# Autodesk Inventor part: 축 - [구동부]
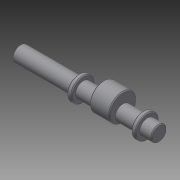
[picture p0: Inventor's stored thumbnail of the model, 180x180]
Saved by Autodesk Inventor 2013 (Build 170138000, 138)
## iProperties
Company: 한국ATC센터
Created: 2014-08
Part Number: 축 - [구동부]
Document SubType Name: Modeling
Designer: KYOUNG IL JANG
Density: 1 g/cm^3
Material: 일반
Author: KYOUNG IL JANG
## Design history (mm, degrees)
sketch "스케치1"
  geometry: L1 (-76.5, 0)-(76.5, 0); L2 (-76.5, 0)-(-76.5, 8.5); L3 (-76.5, 8.5)-(-12.5, 8.5); L4 (-12.5, 8.5)-(-12.5, 13); L5 (-12.5, 13)-(-7.5, 13); L6 (-7.5, 13)-(-7.5, 8.5); L7 (-7.5, 8.5)-(58.5, 8.5); L8 (58.5, 8.5)-(58.5, 13); L9 (58.5, 13)-(63.5, 13); L10 (63.5, 13)-(63.5, 8.5); L11 (63.5, 8.5)-(76.5, 8.5); L12 (76.5, 8.5)-(76.5, 0); 2 further points
  constraints: 24 end point, 5 parallel, 1 coincident, 1 horizontal, 1 midpoint, 1 perpendicular
  dimensions: "d0" = 153 distance of L1.start L1.end (derived); "d2" = 17 diameter of L3 L1; "d3" = 26 diameter of L5 L1; "d4" = 17 diameter of L7 L1; "d5" = 26 diameter of L9 L1; "d6" = 17 diameter of L11 L1; "d7" = 5 distance of L8.end L9.end; "d8" = 5 distance of L4.end L5.end; "d10" = 64 distance of L2.end L3.end; "d11" = 13 distance of L10.end L11.end; "d35" = 66 distance between parallel lines of L8 L6
revolve "회전1" sketch "스케치1" stored, may be unused: angle "d12" = 90 deg
node "작업 평면1"
node "작업 평면2"
node "작업 평면4"
sketch "스케치6"
  geometry: C1 r 15 at (-5, -6); 1 further point
  constraints: 1 centre point, 1 horizontal alignment
  dimensions: "d31" = 30 diameter of C1; "d32" = 5 distance of C1.centre point (0, -6)
extrude "돌출4" join sketch "스케치6" stored distance "d33" = 22; taper "d34" = 0 deg
node "작업 평면3"
sketch "스케치5"
  geometry: L1 (32, 8.5)-(32, -8.5) reference; L2 (32, -2.5)-(14.5, -2.5); L3 (14.5, 2.5)-(32, 2.5); A1 r 2.5 centre (14.5, 0) between (14.5, 2.5) and (14.5, -2.5); 2 further points
  constraints: 4 end point, 2 point on circle, 2 point on line, 2 tangent, 1 centre point, 1 midpoint, 1 parallel, 1 perpendicular
  dimensions: "d23" = 5 distance between parallel lines of L3 L2; "d36" = 20 dimension on A1 L1
extrude "돌출3" cut sketch "스케치5" distance "d25" = 3; taper "d26" = 0 deg
chamfer "모따기1" distance "d27" = 1; stored, may be unused: second distance "d28" = 2, angle "d29" = 45 deg
node "솔리드1"
other parameters: "d13" = 9.5, "d18" = 9.5
